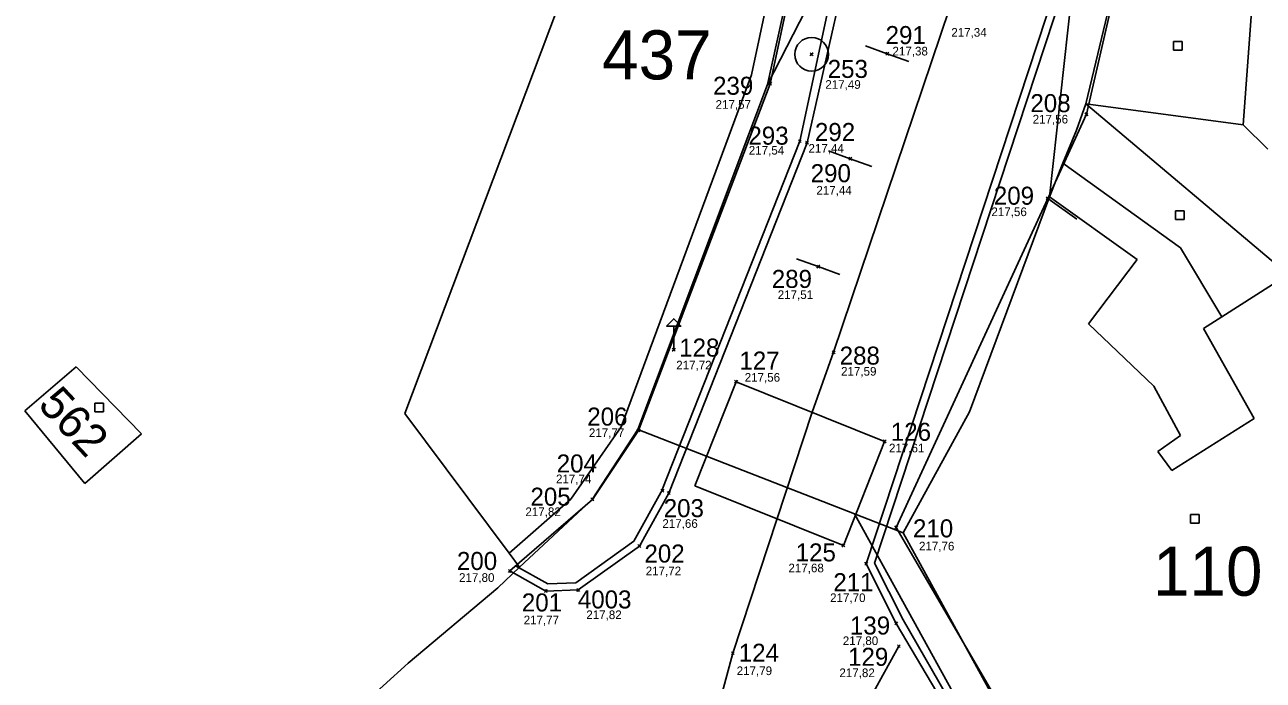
# Model space of a CAD drawing. Extents: x -711879 to -711361, y -1048782 to -1048177.
# Drawn here: x -711666.76 to -711623.84, y -1048524.94 to -1048502.22 of the extents above; entities that cross this region are included whole.
import ezdxf

# ---------------------------------------------------------------- set-up
doc = ezdxf.new("R2010")
doc.units = 0
for name, color, linetype in [('body', 7, 'Continuous'), ('kresba', 7, 'Continuous'), ('Vrstva 1', 7, 'Continuous'), ('Vrstva 15', 7, 'Continuous'), ('Vrstva 2', 7, 'Continuous'), ('Vrstva 20', 7, 'Continuous'), ('Vrstva 25', 7, 'Continuous'), ('Vrstva 41', 7, 'Continuous'), ('Vrstva 46', 7, 'Continuous'), ('výšky', 7, 'Continuous')]:
    doc.layers.add(name, color=color, linetype=linetype)

msp = doc.modelspace()

# ---------------------------------------------------------------- linework, layer by layer
at = {"layer": 'kresba'}
for p, q in [((-711628.01, -1048496.8), (-711629.97, -1048505.32)), ((-711638.74, -1048500.86), (-711639.9, -1048506.25)), ((-711638.43, -1048500.93), (-711639.65, -1048506.31)), ((-711636.87, -1048503.22), (-711637.62, -1048502.95)), ((-711636.12, -1048503.49), (-711636.87, -1048503.22)), ((-711631.31, -1048508.24), (-711629.97, -1048505.32)), ((-711639.9, -1048506.25), (-711644.677, -1048518.357)), ((-711639.65, -1048506.31), (-711644.44, -1048518.45)), ((-711638.15, -1048506.86), (-711638.9, -1048506.59)), ((-711637.4, -1048507.13), (-711638.15, -1048506.86)), ((-711631.31, -1048508.24), (-711636.56, -1048519.64)), ((-711631.31, -1048508.24), (-711630.3, -1048508.96)), ((-711639.26, -1048510.6), (-711640.01, -1048510.33)), ((-711638.51, -1048510.87), (-711639.26, -1048510.6)), ((-711642.11, -1048514.59), (-711643.54, -1048518.2)), ((-711642.11, -1048514.59), (-711636.96, -1048516.66)), ((-711638.39, -1048520.27), (-711636.96, -1048516.66)), ((-711643.54, -1048518.2), (-711638.39, -1048520.27)), ((-711636.56, -1048519.64), (-711631.65, -1048528.05)), ((-711636.32, -1048522.849), (-711633.81, -1048527.19)), ((-711636.56, -1048522.97), (-711632.54, -1048529.76))]:
    msp.add_line(p, q, dxfattribs=at)
for points in [[(-711617.94, -1048449.74), (-711626.67, -1048475.73), (-711634.71, -1048501.65), (-711638.73, -1048513.57), (-711639.471, -1048515.651)], [(-711639.02, -1048486.92), (-711640.25, -1048501.07), (-711640.93, -1048504.26), (-711645.49, -1048516.28), (-711647.09, -1048518.67), (-711649.95, -1048521.15)], [(-711630.73, -1048500.01), (-711637.6, -1048520.9), (-711636.56, -1048522.97)], [(-711630.475, -1048500.094), (-711637.31, -1048520.879), (-711636.32, -1048522.849)], [(-711644.27, -1048513.48), (-711644.27, -1048512.66), (-711644.02, -1048512.66), (-711644.27, -1048512.41), (-711644.52, -1048512.66), (-711644.27, -1048512.66)], [(-711645.33, -1048545.9), (-711645.41, -1048540.21), (-711644.39, -1048532.08), (-711642.22, -1048524), (-711639.471, -1048515.651)], [(-711644.44, -1048518.45), (-711645.46, -1048520.29), (-711647.58, -1048521.81), (-711648.7, -1048521.85), (-711649.95, -1048521.15)], [(-711644.661, -1048518.328), (-711645.653, -1048520.118), (-711647.665, -1048521.56), (-711648.638, -1048521.595), (-711649.748, -1048520.974)], [(-711636.47, -1048523.76), (-711638.58, -1048527.6), (-711639.65, -1048534.27)]]:
    msp.add_lwpolyline(points, dxfattribs=at)
msp.add_circle((-711639.49, -1048503.24), 0.585, dxfattribs=at)
at = {"layer": 'Vrstva 1'}
for p, q in [((-711629.99, -1048504.96), (-711628.96, -1048500.69)), ((-711641.02, -1048504.29), (-711640.33, -1048501.16)), ((-711648.3, -1048501.65), (-711653.59, -1048515.69)), ((-711645.51, -1048516.25), (-711641.02, -1048504.29)), ((-711630.31, -1048505.87), (-711629.99, -1048504.96)), ((-711622.98, -1048510.87), (-711629.99, -1048504.96)), ((-711630.78, -1048507.02), (-711630.31, -1048505.87)), ((-711631.25, -1048508.18), (-711630.78, -1048507.02)), ((-711634.02, -1048515.63), (-711631.25, -1048508.18)), ((-711666.76, -1048515.6), (-711664.98, -1048514.08)), ((-711664.98, -1048514.08), (-711662.71, -1048516.4)), ((-711664.68, -1048518.12), (-711666.76, -1048515.6)), ((-711653.59, -1048515.69), (-711649.97, -1048520.54)), ((-711636.32, -1048519.83), (-711634.02, -1048515.63)), ((-711662.71, -1048516.4), (-711664.68, -1048518.12)), ((-711645.51, -1048516.25), (-711647.1, -1048518.67)), ((-711638.01, -1048519.17), (-711645.51, -1048516.25)), ((-711649.61, -1048521.02), (-711647.1, -1048518.67)), ((-711636.32, -1048519.83), (-711638.01, -1048519.17)), ((-711636.32, -1048519.83), (-711631.75, -1048528.15)), ((-711649.97, -1048520.54), (-711649.61, -1048521.02)), ((-711650.37, -1048521.74), (-711649.61, -1048521.02)), ((-711650.37, -1048521.74), (-711653.47, -1048524.35)), ((-711653.47, -1048524.35), (-711664.7, -1048534.49))]:
    msp.add_line(p, q, dxfattribs=at)
at = {"layer": 'Vrstva 2'}
for p, q in [((-711631.25, -1048508.18), (-711629.85, -1048495.57)), ((-711640.82, -1048500.39), (-711641.58, -1048503.95)), ((-711639.27, -1048500.86), (-711641.02, -1048504.29)), ((-711624.21, -1048501.29), (-711624.54, -1048505.69)), ((-711641.58, -1048503.95), (-711646.09, -1048516.15)), ((-711624.54, -1048505.69), (-711629.99, -1048504.96)), ((-711624.54, -1048505.69), (-711623.68, -1048506.53)), ((-711626.71, -1048509.95), (-711630.78, -1048507.02)), ((-711631.25, -1048508.18), (-711628.21, -1048510.35)), ((-711625.27, -1048512.34), (-711626.71, -1048509.95)), ((-711628.21, -1048510.35), (-711629.89, -1048512.59)), ((-711625.27, -1048512.34), (-711622.98, -1048510.87)), ((-711625.91, -1048512.75), (-711625.27, -1048512.34)), ((-711629.89, -1048512.59), (-711627.63, -1048514.75)), ((-711624.15, -1048515.87), (-711625.91, -1048512.75)), ((-711627.63, -1048514.75), (-711626.71, -1048516.45)), ((-711627.01, -1048517.67), (-711624.15, -1048515.87)), ((-711646.09, -1048516.15), (-711647.84, -1048518.66)), ((-711626.71, -1048516.45), (-711627.49, -1048517.01)), ((-711627.49, -1048517.01), (-711627.01, -1048517.67)), ((-711647.84, -1048518.66), (-711649.97, -1048520.54)), ((-711631.89, -1048530.24), (-711638.01, -1048519.17))]:
    msp.add_line(p, q, dxfattribs=at)
at = {"layer": 'Vrstva 20'}
for p, q in [((-711639.49, -1048503.24), (-711639.54, -1048503.19)), ((-711639.49, -1048503.24), (-711639.54, -1048503.29)), ((-711639.49, -1048503.24), (-711639.44, -1048503.19)), ((-711639.49, -1048503.24), (-711639.44, -1048503.29)), ((-711636.87, -1048503.22), (-711636.92, -1048503.17)), ((-711636.87, -1048503.22), (-711636.92, -1048503.27)), ((-711636.87, -1048503.22), (-711636.82, -1048503.17)), ((-711636.87, -1048503.22), (-711636.82, -1048503.27)), ((-711640.93, -1048504.26), (-711640.98, -1048504.21)), ((-711640.93, -1048504.26), (-711640.98, -1048504.31)), ((-711640.93, -1048504.26), (-711640.88, -1048504.21)), ((-711640.93, -1048504.26), (-711640.88, -1048504.31)), ((-711629.97, -1048505.32), (-711630.02, -1048505.27)), ((-711629.97, -1048505.32), (-711629.92, -1048505.27)), ((-711629.97, -1048505.32), (-711630.02, -1048505.37)), ((-711629.97, -1048505.32), (-711629.92, -1048505.37)), ((-711639.9, -1048506.25), (-711639.95, -1048506.2)), ((-711639.9, -1048506.25), (-711639.95, -1048506.3)), ((-711639.9, -1048506.25), (-711639.85, -1048506.2)), ((-711639.9, -1048506.25), (-711639.85, -1048506.3)), ((-711639.65, -1048506.31), (-711639.7, -1048506.26)), ((-711639.65, -1048506.31), (-711639.7, -1048506.36)), ((-711639.65, -1048506.31), (-711639.6, -1048506.26)), ((-711639.65, -1048506.31), (-711639.6, -1048506.36)), ((-711638.15, -1048506.86), (-711638.2, -1048506.81)), ((-711638.15, -1048506.86), (-711638.2, -1048506.91)), ((-711638.15, -1048506.86), (-711638.1, -1048506.81)), ((-711638.15, -1048506.86), (-711638.1, -1048506.91)), ((-711631.31, -1048508.24), (-711631.36, -1048508.19)), ((-711631.31, -1048508.24), (-711631.36, -1048508.29)), ((-711631.31, -1048508.24), (-711631.26, -1048508.19)), ((-711631.31, -1048508.24), (-711631.26, -1048508.29)), ((-711639.26, -1048510.6), (-711639.31, -1048510.55)), ((-711639.26, -1048510.6), (-711639.31, -1048510.65)), ((-711639.26, -1048510.6), (-711639.21, -1048510.55)), ((-711639.26, -1048510.6), (-711639.21, -1048510.65)), ((-711644.27, -1048513.48), (-711644.32, -1048513.43)), ((-711644.27, -1048513.48), (-711644.22, -1048513.43)), ((-711644.27, -1048513.48), (-711644.32, -1048513.53)), ((-711644.27, -1048513.48), (-711644.22, -1048513.53)), ((-711638.73, -1048513.57), (-711638.78, -1048513.52)), ((-711638.73, -1048513.57), (-711638.78, -1048513.62)), ((-711638.73, -1048513.57), (-711638.68, -1048513.52)), ((-711638.73, -1048513.57), (-711638.68, -1048513.62)), ((-711642.11, -1048514.59), (-711642.16, -1048514.54)), ((-711642.11, -1048514.59), (-711642.16, -1048514.64)), ((-711642.11, -1048514.59), (-711642.06, -1048514.54)), ((-711642.11, -1048514.59), (-711642.06, -1048514.64)), ((-711645.49, -1048516.28), (-711645.54, -1048516.23)), ((-711645.49, -1048516.28), (-711645.54, -1048516.33)), ((-711645.49, -1048516.28), (-711645.44, -1048516.23)), ((-711645.49, -1048516.28), (-711645.44, -1048516.33)), ((-711636.96, -1048516.66), (-711637.01, -1048516.61)), ((-711636.96, -1048516.66), (-711637.01, -1048516.71)), ((-711636.96, -1048516.66), (-711636.91, -1048516.61)), ((-711636.96, -1048516.66), (-711636.91, -1048516.71)), ((-711644.66, -1048518.37), (-711644.71, -1048518.32)), ((-711644.66, -1048518.37), (-711644.71, -1048518.42)), ((-711644.66, -1048518.37), (-711644.61, -1048518.32)), ((-711644.66, -1048518.37), (-711644.61, -1048518.42)), ((-711644.44, -1048518.45), (-711644.49, -1048518.4)), ((-711644.44, -1048518.45), (-711644.49, -1048518.5)), ((-711644.44, -1048518.45), (-711644.39, -1048518.4)), ((-711644.44, -1048518.45), (-711644.39, -1048518.5)), ((-711647.09, -1048518.67), (-711647.14, -1048518.62)), ((-711647.09, -1048518.67), (-711647.14, -1048518.72)), ((-711647.09, -1048518.67), (-711647.04, -1048518.62)), ((-711647.09, -1048518.67), (-711647.04, -1048518.72)), ((-711636.56, -1048519.64), (-711636.61, -1048519.59)), ((-711636.56, -1048519.64), (-711636.61, -1048519.69)), ((-711636.56, -1048519.64), (-711636.51, -1048519.59)), ((-711636.56, -1048519.64), (-711636.51, -1048519.69)), ((-711645.46, -1048520.29), (-711645.51, -1048520.24)), ((-711645.46, -1048520.29), (-711645.51, -1048520.34)), ((-711645.46, -1048520.29), (-711645.41, -1048520.24)), ((-711645.46, -1048520.29), (-711645.41, -1048520.34)), ((-711638.39, -1048520.27), (-711638.44, -1048520.22)), ((-711638.39, -1048520.27), (-711638.44, -1048520.32)), ((-711638.39, -1048520.27), (-711638.34, -1048520.22)), ((-711638.39, -1048520.27), (-711638.34, -1048520.32)), ((-711649.95, -1048521.15), (-711650, -1048521.1)), ((-711649.95, -1048521.15), (-711650, -1048521.2)), ((-711649.95, -1048521.15), (-711649.9, -1048521.1)), ((-711649.95, -1048521.15), (-711649.9, -1048521.2)), ((-711637.6, -1048520.9), (-711637.65, -1048520.85)), ((-711637.6, -1048520.9), (-711637.65, -1048520.95)), ((-711637.6, -1048520.9), (-711637.55, -1048520.85)), ((-711637.6, -1048520.9), (-711637.55, -1048520.95)), ((-711648.7, -1048521.85), (-711648.75, -1048521.8)), ((-711648.7, -1048521.85), (-711648.75, -1048521.9)), ((-711648.7, -1048521.85), (-711648.65, -1048521.8)), ((-711648.7, -1048521.85), (-711648.65, -1048521.9)), ((-711647.58, -1048521.81), (-711647.63, -1048521.76)), ((-711647.58, -1048521.81), (-711647.63, -1048521.86)), ((-711647.58, -1048521.81), (-711647.53, -1048521.76)), ((-711647.58, -1048521.81), (-711647.53, -1048521.86)), ((-711636.56, -1048522.97), (-711636.61, -1048522.92)), ((-711636.56, -1048522.97), (-711636.61, -1048523.02)), ((-711636.56, -1048522.97), (-711636.51, -1048522.92)), ((-711636.56, -1048522.97), (-711636.51, -1048523.02)), ((-711636.47, -1048523.76), (-711636.52, -1048523.71)), ((-711636.47, -1048523.76), (-711636.42, -1048523.71)), ((-711642.22, -1048524), (-711642.27, -1048523.95)), ((-711642.22, -1048524), (-711642.27, -1048524.05)), ((-711642.22, -1048524), (-711642.17, -1048523.95)), ((-711642.22, -1048524), (-711642.17, -1048524.05)), ((-711636.47, -1048523.76), (-711636.52, -1048523.81)), ((-711636.47, -1048523.76), (-711636.42, -1048523.81))]:
    msp.add_line(p, q, dxfattribs=at)
at = {"layer": 'Vrstva 25'}
for p, q in [((-711626.95, -1048502.8), (-711626.65, -1048502.8)), ((-711626.95, -1048503.1), (-711626.95, -1048502.8)), ((-711626.65, -1048503.1), (-711626.95, -1048503.1)), ((-711626.65, -1048502.8), (-711626.65, -1048503.1)), ((-711626.88, -1048508.67), (-711626.58, -1048508.67)), ((-711626.88, -1048508.97), (-711626.88, -1048508.67)), ((-711626.58, -1048508.67), (-711626.58, -1048508.97)), ((-711626.58, -1048508.97), (-711626.88, -1048508.97)), ((-711664.33, -1048515.33), (-711664.03, -1048515.33)), ((-711664.33, -1048515.63), (-711664.33, -1048515.33)), ((-711664.03, -1048515.33), (-711664.03, -1048515.63)), ((-711664.03, -1048515.63), (-711664.33, -1048515.63)), ((-711626.36, -1048519.19), (-711626.06, -1048519.19)), ((-711626.36, -1048519.49), (-711626.36, -1048519.19)), ((-711626.06, -1048519.19), (-711626.06, -1048519.49)), ((-711626.06, -1048519.49), (-711626.36, -1048519.49))]:
    msp.add_line(p, q, dxfattribs=at)
at = {"layer": 'Vrstva 41'}
for p, q in [((-711639.49, -1048503.24), (-711639.49, -1048503.24)), ((-711636.87, -1048503.22), (-711636.87, -1048503.22)), ((-711640.93, -1048504.26), (-711640.93, -1048504.26)), ((-711629.97, -1048505.32), (-711629.97, -1048505.32)), ((-711639.9, -1048506.25), (-711639.9, -1048506.25)), ((-711639.65, -1048506.31), (-711639.65, -1048506.31)), ((-711638.15, -1048506.86), (-711638.15, -1048506.86)), ((-711631.31, -1048508.24), (-711631.31, -1048508.24)), ((-711639.26, -1048510.6), (-711639.26, -1048510.6)), ((-711644.27, -1048513.48), (-711644.27, -1048513.48)), ((-711638.73, -1048513.57), (-711638.73, -1048513.57)), ((-711642.11, -1048514.59), (-711642.11, -1048514.59)), ((-711645.49, -1048516.28), (-711645.49, -1048516.28)), ((-711636.96, -1048516.66), (-711636.96, -1048516.66)), ((-711644.66, -1048518.37), (-711644.66, -1048518.37)), ((-711644.44, -1048518.45), (-711644.44, -1048518.45)), ((-711647.09, -1048518.67), (-711647.09, -1048518.67)), ((-711636.56, -1048519.64), (-711636.56, -1048519.64)), ((-711645.46, -1048520.29), (-711645.46, -1048520.29)), ((-711638.39, -1048520.27), (-711638.39, -1048520.27)), ((-711649.95, -1048521.15), (-711649.95, -1048521.15)), ((-711637.6, -1048520.9), (-711637.6, -1048520.9)), ((-711648.7, -1048521.85), (-711648.7, -1048521.85)), ((-711647.58, -1048521.81), (-711647.58, -1048521.81)), ((-711636.56, -1048522.97), (-711636.56, -1048522.97)), ((-711642.22, -1048524), (-711642.22, -1048524)), ((-711636.47, -1048523.76), (-711636.47, -1048523.76))]:
    msp.add_line(p, q, dxfattribs=at)
at = {"layer": 'Vrstva 46'}
msp.add_line((-711624.54, -1048505.69), (-711624.54, -1048505.69), dxfattribs=at)

# ---------------------------------------------------------------- texts
at = {"layer": 'body'}
for s, p in [('291', (-711636.927, -1048502.886)), ('253', (-711638.934, -1048504.059)), ('239', (-711642.906, -1048504.643)), ('208', (-711631.91, -1048505.246)), ('292', (-711639.376, -1048506.247)), ('293', (-711641.682, -1048506.374)), ('290', (-711639.524, -1048507.674)), ('209', (-711633.176, -1048508.455)), ('289', (-711640.872, -1048511.339)), ('128', (-711644.08, -1048513.72)), ('288', (-711638.519, -1048513.998)), ('127', (-711641.994, -1048514.171)), ('206', (-711647.266, -1048516.112)), ('126', (-711636.746, -1048516.639)), ('204', (-711648.325, -1048517.737)), ('205', (-711649.235, -1048518.889)), ('203', (-711644.617, -1048519.287)), ('210', (-711635.979, -1048519.987)), ('202', (-711645.285, -1048520.86)), ('125', (-711640.044, -1048520.821)), ('200', (-711651.783, -1048521.118)), ('211', (-711638.738, -1048521.853)), ('201', (-711649.534, -1048522.556)), ('4003', (-711647.593, -1048522.451)), ('139', (-711638.163, -1048523.355)), ('124', (-711642.016, -1048524.3)), ('129', (-711638.228, -1048524.44))]:
    msp.add_text(s, height=0.625, dxfattribs=at).set_placement(p)
at = {"layer": 'Vrstva 15'}
for s, p in [('437', (-711646.75, -1048504.11)), ('110', (-711627.66, -1048522.01))]:
    msp.add_text(s, height=1.7, dxfattribs=at).set_placement(p)
msp.add_text('562', height=1.14, rotation=313.1283, dxfattribs=at).set_placement((-711666.343, -1048515.426))
at = {"layer": 'výšky'}
for s, p in [('217,34', (-711634.65, -1048502.63)), ('217,38', (-711636.689, -1048503.28)), ('217,49', (-711639.016, -1048504.437)), ('217,57', (-711642.82, -1048505.13)), ('217,56', (-711631.83, -1048505.64)), ('217,54', (-711641.668, -1048506.718)), ('217,44', (-711639.6, -1048506.65)), ('217,44', (-711639.326, -1048508.104)), ('217,56', (-711633.26, -1048508.85)), ('217,51', (-711640.665, -1048511.723)), ('217,72', (-711644.184, -1048514.165)), ('217,56', (-711641.81, -1048514.59)), ('217,59', (-711638.47, -1048514.38)), ('217,77', (-711647.21, -1048516.51)), ('217,61', (-711636.81, -1048517.04)), ('217,74', (-711648.35, -1048518.11)), ('217,82', (-711649.41, -1048519.25)), ('217,66', (-711644.663, -1048519.657)), ('217,76', (-711635.77, -1048520.44)), ('217,72', (-711645.24, -1048521.3)), ('217,68', (-711640.294, -1048521.198)), ('217,80', (-711651.71, -1048521.53)), ('217,70', (-711638.85, -1048522.23)), ('217,77', (-711649.47, -1048523)), ('217,82', (-711647.3, -1048522.82)), ('217,80', (-711638.41, -1048523.72)), ('217,79', (-711642.088, -1048524.762)), ('217,82', (-711638.528, -1048524.832))]:
    msp.add_text(s, height=0.3, dxfattribs=at).set_placement(p)

doc.saveas('drawing.dxf')
